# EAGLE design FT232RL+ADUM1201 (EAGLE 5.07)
FARNELL: 1696539
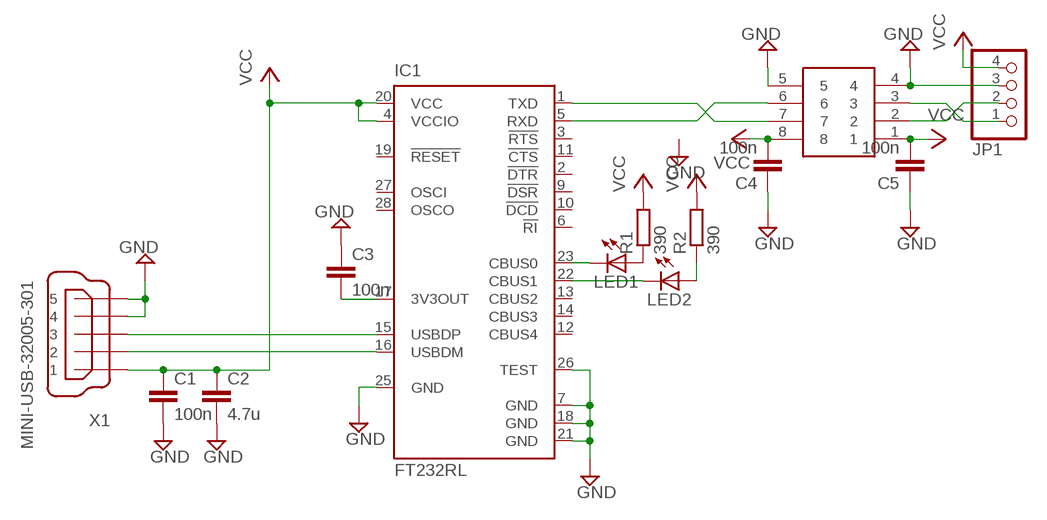
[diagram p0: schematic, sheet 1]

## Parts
C1  100n  C-EUC0603  [C0603]
C2  4.7u  C-EUC0603  [C0603]
C3  100n  C-EUC0603  [C0603]
C4  100n  C-EUC0603  [C0603]
C5  100n  C-EUC0603  [C0603]
IC1  FT232RL  [SSOP28]
JP1  PINHD-1X4  [1X04]
LED1  LEDCHIP-LED0805  [CHIP-LED0805]
LED2  LEDCHIP-LED0805  [CHIP-LED0805]
R1  390  R-EU_R0603  [R0603]
R2  390  R-EU_R0603  [R0603]
U$1  8PIN-SOIC  [SO08]
X1  MINI-USB-32005-301  [32005-301]

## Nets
GND: C1.2 C2.2 C3.1 C4.1 IC1.7(GND) IC1.18(GND) IC1.21(GND) IC1.25(GND) IC1.26(TEST) U$1.5 X1.4 X1.5
GND2: C5.1 JP1.3 U$1.4 ; supply symbol labelled GND
N$1: IC1.16(USBDM) X1.2
N$2: IC1.15(USBDP) X1.3
N$3: LED1.A R1.1
N$4: IC1.1(TXD) U$1.7
N$5: C3.2 IC1.17(3V3OUT)
N$6: IC1.5(RXD) U$1.6
N$7: JP1.1 U$1.3
N$8: JP1.2 U$1.2
N$9: IC1.23(CBUS0) LED1.C
N$10: IC1.22(CBUS1) LED2.C
N$11: LED2.A R2.1
VCC: C1.1 C2.1 C4.2 IC1.4(VCCIO) IC1.20(VCC) R1.2 R2.2 U$1.8 X1.1
VCC2: C5.2 JP1.4 U$1.1 ; supply symbol labelled VCC
Unconnected: IC1.2(!DTR) IC1.3(!RTS) IC1.6(!RI) IC1.9(!DSR) IC1.10(!DCD) IC1.11(!CTS) IC1.12(CBUS4) IC1.13(CBUS2) IC1.14(CBUS3) IC1.19(!RESET) IC1.27(OSCI) IC1.28(OSCO)

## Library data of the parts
C1-C5 = rcl:C-EU: CAPACITOR, European symbol
IC1 = ftdichip:FT232R: Source: http://www.ftdichip.com/Documents/DataSheets/DS_FT232R_v104.pdf
JP1 = pinhead:PINHD-1X4: PIN HEADER
LED1 LED2 = led:LED: LED
R1 R2 = rcl:R-EU_: RESISTOR, European symbol
U$1 = generic-packages:8PIN
X1 = con-cypressindustries:MINI-USB-: MINI USB-B Conector Source: www.cypressindustries.com

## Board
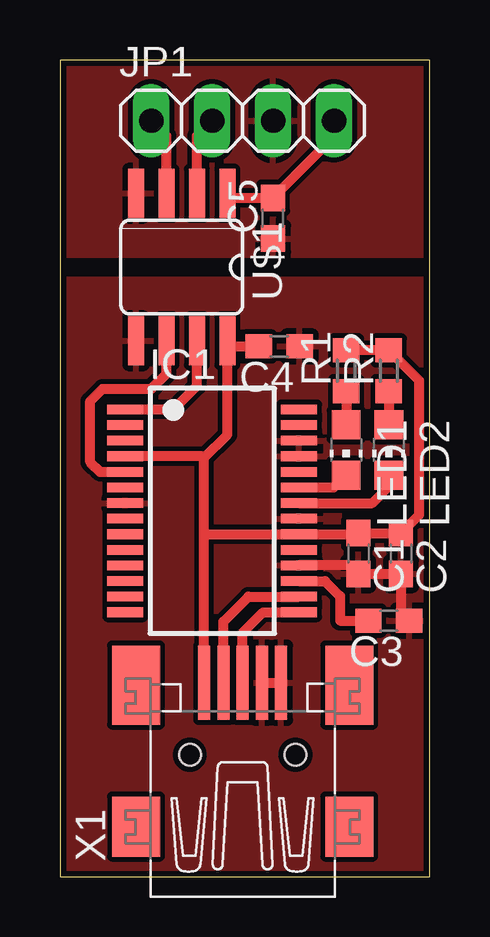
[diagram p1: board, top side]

Size 15.42 x 34.03 mm. Coordinates in mm from the lower left corner, seen from the top.
Outline: 0,0 15.42,0 15.42,34.03 0,34.03 0,0
Copper layers (1*16): Top 0.035mm / dielectric 1.5mm / Bottom 0.035mm
Design rules "default *": minimum track width 10mil, minimum drill 24mil, track to track 8mil, track to pad 8mil, pad to pad 8mil, via to via 8mil, smd to smd 8mil, copper to edge 10mil, drill to drill 8mil, minimum pad ring 10mil, minimum via ring 8mil, stop-mask expansion 4mil, vias tented up to drill 0mil, thermal gap 10mil

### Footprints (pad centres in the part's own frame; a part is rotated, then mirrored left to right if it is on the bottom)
C0603 = smd 1.1 x 1: 1 -0.85,0; 2 0.85,0
SSOP28 = smd 0.4 x 1.5: 1 -4.225,-3.625; 2 -3.575,-3.625; 3 -2.925,-3.625; 4 -2.275,-3.625; 5 -1.625,-3.625; 6 -0.975,-3.625; 7 -0.325,-3.625; 8 0.325,-3.625; 9 0.975,-3.625; 10 1.625,-3.625; 11 2.275,-3.625; 12 2.925,-3.625; 13 3.575,-3.625; 14 4.225,-3.625; 15 4.225,3.625; 16 3.575,3.625; 17 2.925,3.625; 18 2.275,3.625; 19 1.625,3.625; 20 0.975,3.625; 21 0.325,3.625; 22 -0.325,3.625; 23 -0.975,3.625; 24 -1.625,3.625; 25 -2.275,3.625; 26 -2.925,3.625; 27 -3.575,3.625; 28 -4.225,3.625
1X04 = drill 1.016 long: 1 -3.81,0; 2 -1.27,0; 3 1.27,0; 4 3.81,0
CHIP-LED0805 = smd 1.2 x 1.2: A 0,-1.05; C 0,1.05
R0603 = smd 1 x 1.1: 1 -0.85,0; 2 0.85,0
SO08 = smd 0.66 x 2.032: 1 -1.905,-3.073; 2 -0.635,-3.073; 3 0.635,-3.073; 4 1.905,-3.073; 5 1.905,3.073; 6 0.635,3.073; 7 -0.635,3.073; 8 -1.905,3.073
32005-301 = smd 3.1 x 0.5: 1 3,1.6; 2 3,0.8; 3 3,0; 4 3,-0.8; 5 3,-1.6 | smd 2.5 x 2: M1 -3,-4.45; M2 -3,4.45 | smd 3.3 x 2: M3 2.9,4.45; M4 2.9,-4.45 | hole 0.9: 0,2.2; 0,-2.2

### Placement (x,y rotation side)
C1  12.45,13.46 270 top
C2  14.22,13.46 270 top
C3  13.72,10.67 180 top
C4  9.14,22.1 180 top
C5  8.89,27.43 90 top
IC1  6.35,15.24 270 top
JP1  7.62,31.5 0 top
LED1  11.94,17.78 180 top
LED2  13.72,17.78 180 top
R1  11.94,21.08 90 top
R2  13.72,21.08 90 top
U$1  5.08,25.4 180 top
X1  7.62,5.08 90 top

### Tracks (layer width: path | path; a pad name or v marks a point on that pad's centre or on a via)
GND
  Top 0.406: C3.1 14.22,11.09 C2.2 C1.2 12.09,12.96 IC1.18 | X1.4 X1.5
  pour Top: 0,0 0,24.89 15.24,24.89 15.24,0
GND2
  pour Top: 0,25.91 15.24,25.91 15.24,34.29 0,34.29
N$1
  Top 0.406: X1.2 6.82,10.63 7.86,11.66 IC1.16
N$2
  Top 0.406: X1.3 7.62,10.16 8.47,11.02 IC1.15
N$3
  Top 0.406: R1.1 LED1.A
N$4
  Top 0.406: U$1.7 5.71,20.45 4.73,19.46 IC1.1
N$5
  Top 0.406: C3.2 11.68,10.67 11.68,11.68 11.05,12.31 IC1.17
N$6
  Top 0.406: U$1.6 4.45,20.95 3.81,20.32 1.78,20.32 1.27,19.81 1.27,17.27 1.68,16.86 IC1.5
N$7
  Top 0.406: U$1.3 4.45,30.86 JP1.1
N$8
  Top 0.406: U$1.2 5.71,30.86 JP1.2
N$9
  Top 0.406: IC1.23 11.42,16.21 LED1.C
N$10
  Top 0.406: IC1.22 13.03,15.56 13.72,16.26 LED2.C
N$11
  Top 0.406: R2.1 LED2.A
VCC
  Top 0.406: X1.1 6.02,14.27 | 11.77,21.93 R1.2 R2.2 14.99,20.66 14.99,15.07 C2.1 C1.1 12.4,14.27 IC1.20 6.02,14.27 | 6.02,14.27 6.02,17.45 | 6.02,17.45 6.99,18.41 U$1.8 7.21,22.1 C4.2 | IC1.4 5.96,17.52 6.02,17.45
VCC2
  Top 0.406: U$1.1 7.18,28.28 C5.2 11.43,30.82 JP1.4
